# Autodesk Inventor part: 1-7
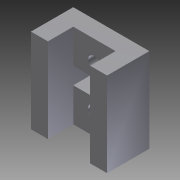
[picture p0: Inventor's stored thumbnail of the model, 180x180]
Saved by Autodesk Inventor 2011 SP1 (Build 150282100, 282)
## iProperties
Created: 2014-02
Part Number: 1-7
Document SubType Name: Modeling
Designer: Administrator
Density: 1 g/cm^3
Author: Administrator
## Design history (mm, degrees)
sketch "草图1"
  geometry: L1 (-5, 0)-(-5, -6); L2 (-5, 0)-(5, 0); L3 (5, 0)-(5, -6); L4 (5, -6)-(9, -6); L5 (-5, -6)-(-9, -6); L6 (-9, -6)-(-9, 4); L7 (-9, 4)-(9, 4); L8 (9, 4)-(9, -6); 2 further points
  constraints: 16 end point, 4 perpendicular, 2 coincident, 2 parallel, 1 collinear, 1 midpoint, 1 vertical
  dimensions: "d0" = 6 distance of L1.start L1.end; "d1" = 10 distance of L1.start L2.end; "d2" = 6 distance of L2.end L3.end; "d3" = 4 distance of L3.end L4.end; "d4" = 4 distance of L1.end L5.end; "d5" = 10 distance of L5.end L6.end
extrude "拉伸1" new body sketch "草图1" distance "d6" = 20; taper "d7" = 0 deg
sketch "草图2"
  geometry: C1 r 1.5 at (9, -15); C2 r 1.5 at (9, -5); 1 further point
  constraints: 2 centre point
  dimensions: "d9" = 3 diameter of C1; "d10" = 3 diameter of C2
extrude "拉伸2" cut sketch "草图2" stored distance "d11" = 20; taper "d12" = 0 deg
sketch "草图3"
  geometry: L1 (0, 0)-(0, 20) reference; L2 (10, 0)-(10, 20) reference; L3 (10, 8)-(0, 8); L4 (0, 8)-(0, 12); L5 (0, 12)-(10, 12); L6 (10, 12)-(10, 8); L7 (10, 0)-(10, 20) reference; L8 (0, 0)-(0, 20) reference; 1 further point
  constraints: 8 end point, 2 parallel, 2 point on line, 1 horizontal, 1 perpendicular
extrude "拉伸3" cut sketch "草图3" stored distance "d13" = 20; taper "d14" = 0 deg
node "实体1"
